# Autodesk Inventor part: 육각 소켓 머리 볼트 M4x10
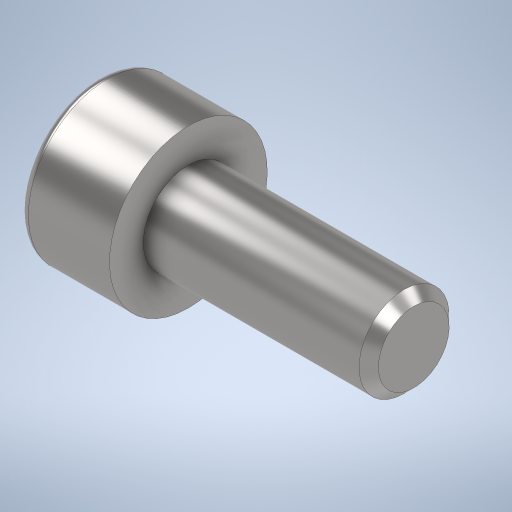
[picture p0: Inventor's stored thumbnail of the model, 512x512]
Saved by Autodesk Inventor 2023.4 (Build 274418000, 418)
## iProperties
Created: 2024-05
Part Number: 육각 소켓 머리 볼트 M4x10
Material: 강철, 연강
Description: 6각머리 태핑 나사
Document SubType Name: Modeling
Designer: EDU-001
Density: 7.85 g/cm^3
Appearance: 기본값
Author: jhkim
Sending System: Autodesk Inventor 2025
Preprocessor: ST-DEVELOPER v20
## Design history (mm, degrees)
node "육각 소켓 머리 볼트 M4x101"
node "솔리드1"
body "Solid1"
